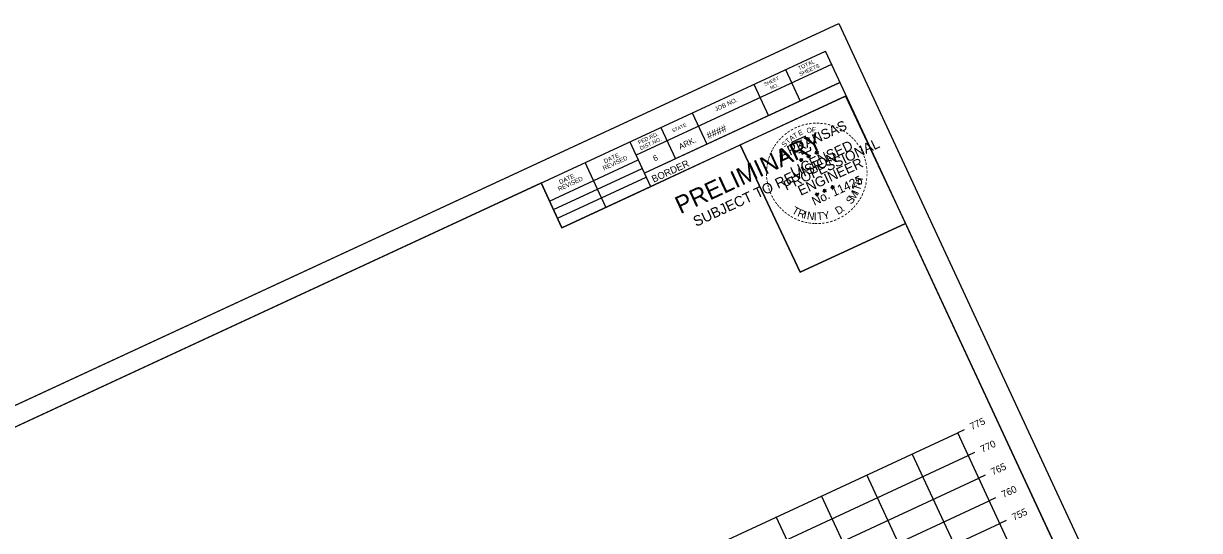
# Model space of a CAD drawing. Extents: x 1354696 to 1366163, y 660729 to 670380.
# Drawn here: x 1357962.4 to 1358197.6, y 666355.4 to 666456.9 of the extents above; entities that cross this region are included whole.
import ezdxf

# ---------------------------------------------------------------- set-up
doc = ezdxf.new("R2010")
doc.units = 0
for name, color, linetype in [('R_Axis', 7, 'Continuous'), ('R_Axis Annot', 7, 'Continuous'), ('R_Border', 7, 'Continuous'), ('R_Border PE', 7, 'Continuous'), ('R_Border Prem', 7, 'Continuous'), ('R_Grid', 7, 'Continuous'), ('R_No Plot', 7, 'Continuous')]:
    doc.layers.add(name, color=color, linetype=linetype)

msp = doc.modelspace()

# ---------------------------------------------------------------- linework, layer by layer
at = {"layer": 'R_Axis'}
for p, q in [((1358150.49, 666375.58), (1358149.22, 666374.99)), ((1358168.17, 666334.17), (1358149.22, 666374.99)), ((1358152.59, 666371.04), (1358151.32, 666370.46)), ((1358154.7, 666366.51), (1358153.43, 666365.92)), ((1358156.8, 666361.97), (1358155.53, 666361.39)), ((1358158.91, 666357.44), (1358157.64, 666356.85))]:
    msp.add_line(p, q, dxfattribs=at)
at = {"layer": 'R_Border'}
for p, q in [((1357835.98, 666318.27), (1358122.76, 666451.41)), ((1358209.28, 666265.06), (1358122.76, 666451.41)), ((1358123.99, 666448.75), (1358084.9, 666430.6)), ((1358123.99, 666448.76), (1358123.99, 666448.76)), ((1358114.77, 666447.71), (1358117.7, 666441.41)), ((1358125.68, 666445.12), (1358086.59, 666426.97)), ((1358089.27, 666428.22), (1358125.68, 666445.12)), ((1358108.48, 666444.78), (1358111.4, 666438.49)), ((1358126.92, 666442.45), (1358070.1, 666416.07)), ((1358096.16, 666439.07), (1358099.08, 666432.77)), ((1358089.87, 666436.14), (1358092.79, 666429.85)), ((1358083.66, 666433.26), (1358087.82, 666424.3)), ((1358067.63, 666421.39), (1358085.36, 666429.62)), ((1358078.88, 666420.15), (1358074.72, 666429.11)), ((1358068.42, 666419.7), (1358086.14, 666427.93)), ((1358070.1, 666416.07), (1358065.94, 666425.04)), ((1358069.23, 666417.94), (1358086.96, 666426.17)), ((1357974.42, 666382.26), (1357974.42, 666382.26)), ((1357974.42, 666382.26), (1357974.42, 666382.26))]:
    msp.add_line(p, q, dxfattribs=at)
at = {"layer": 'R_Border PE'}
for p, q in [((1358117.56, 666429.57), (1358117.8, 666429.63)), ((1358117.56, 666429.57), (1358117.92, 666429.61)), ((1358117.56, 666429.57), (1358117.82, 666429.56)), ((1358117.92, 666429.61), (1358117.77, 666429.94)), ((1358117.77, 666429.94), (1358117.92, 666429.74)), ((1358117.77, 666429.94), (1358117.83, 666429.7)), ((1358117.85, 666429.25), (1358117.92, 666429.61)), ((1358117.85, 666429.25), (1358117.95, 666429.54)), ((1358117.85, 666429.25), (1358117.86, 666429.53)), ((1358118.19, 666429.86), (1358117.92, 666429.61)), ((1358118.24, 666429.43), (1358117.92, 666429.61)), ((1358118.19, 666429.86), (1358117.95, 666429.7)), ((1358118.24, 666429.43), (1358117.95, 666429.54)), ((1358118.24, 666429.43), (1358117.99, 666429.64)), ((1358118.19, 666429.86), (1358118.05, 666429.68)), ((1358119.07, 666430.27), (1358119.32, 666430.34)), ((1358119.07, 666430.27), (1358119.43, 666430.32)), ((1358119.07, 666430.27), (1358119.34, 666430.26)), ((1358119.43, 666430.32), (1358119.28, 666430.65)), ((1358119.28, 666430.65), (1358119.43, 666430.44)), ((1358119.28, 666430.65), (1358119.35, 666430.4)), ((1358119.36, 666429.96), (1358119.43, 666430.32)), ((1358119.36, 666429.96), (1358119.47, 666430.24)), ((1358119.36, 666429.96), (1358119.37, 666430.23)), ((1358119.7, 666430.56), (1358119.43, 666430.32)), ((1358119.75, 666430.14), (1358119.43, 666430.32)), ((1358119.7, 666430.56), (1358119.46, 666430.4)), ((1358119.75, 666430.14), (1358119.47, 666430.24)), ((1358119.75, 666430.14), (1358119.51, 666430.34)), ((1358119.7, 666430.56), (1358119.56, 666430.39)), ((1358120.68, 666431), (1358120.92, 666431.07)), ((1358120.68, 666431), (1358121.04, 666431.05)), ((1358120.68, 666431), (1358120.94, 666430.99)), ((1358121.04, 666431.05), (1358120.89, 666431.38)), ((1358120.89, 666431.38), (1358121.04, 666431.17)), ((1358120.89, 666431.38), (1358120.95, 666431.13)), ((1358120.97, 666430.69), (1358121.04, 666431.05)), ((1358120.97, 666430.69), (1358121.07, 666430.98)), ((1358120.97, 666430.69), (1358120.98, 666430.96)), ((1358121.31, 666431.3), (1358121.04, 666431.05)), ((1358121.36, 666430.87), (1358121.04, 666431.05)), ((1358121.31, 666431.3), (1358121.07, 666431.13)), ((1358121.36, 666430.87), (1358121.07, 666430.97)), ((1358121.36, 666430.87), (1358121.11, 666431.08)), ((1358121.31, 666431.3), (1358121.17, 666431.12)), ((1358124.23, 666424.18), (1358124.07, 666424.51)), ((1358124.07, 666424.51), (1358124.22, 666424.31)), ((1358124.07, 666424.51), (1358124.14, 666424.27)), ((1358124.49, 666424.43), (1358124.23, 666424.18)), ((1358124.49, 666424.43), (1358124.25, 666424.26)), ((1358124.49, 666424.43), (1358124.35, 666424.25)), ((1358120.74, 666422.7), (1358120.99, 666422.76)), ((1358120.74, 666422.7), (1358121.1, 666422.74)), ((1358120.74, 666422.7), (1358121.01, 666422.69)), ((1358121.1, 666422.74), (1358120.95, 666423.07)), ((1358120.95, 666423.07), (1358121.1, 666422.87)), ((1358120.95, 666423.07), (1358121.02, 666422.83)), ((1358121.03, 666422.38), (1358121.1, 666422.74)), ((1358121.03, 666422.38), (1358121.14, 666422.67)), ((1358121.03, 666422.38), (1358121.05, 666422.66)), ((1358121.37, 666422.99), (1358121.1, 666422.74)), ((1358121.42, 666422.56), (1358121.1, 666422.74)), ((1358121.37, 666422.99), (1358121.13, 666422.83)), ((1358121.42, 666422.56), (1358121.14, 666422.67)), ((1358121.42, 666422.56), (1358121.18, 666422.77)), ((1358121.37, 666422.99), (1358121.23, 666422.81)), ((1358122.26, 666423.4), (1358122.5, 666423.47)), ((1358122.26, 666423.4), (1358122.62, 666423.45)), ((1358122.26, 666423.4), (1358122.52, 666423.39)), ((1358122.62, 666423.45), (1358122.46, 666423.78)), ((1358122.46, 666423.78), (1358122.61, 666423.57)), ((1358122.46, 666423.78), (1358122.53, 666423.53)), ((1358122.55, 666423.09), (1358122.62, 666423.45)), ((1358122.55, 666423.09), (1358122.65, 666423.37)), ((1358122.55, 666423.09), (1358122.56, 666423.36)), ((1358122.89, 666423.69), (1358122.62, 666423.45)), ((1358122.94, 666423.27), (1358122.62, 666423.45)), ((1358122.89, 666423.69), (1358122.65, 666423.53)), ((1358122.94, 666423.27), (1358122.65, 666423.37)), ((1358122.94, 666423.27), (1358122.69, 666423.47)), ((1358122.89, 666423.69), (1358122.74, 666423.51)), ((1358123.86, 666424.13), (1358124.11, 666424.2)), ((1358123.86, 666424.13), (1358124.23, 666424.18)), ((1358123.86, 666424.13), (1358124.13, 666424.12)), ((1358124.15, 666423.82), (1358124.23, 666424.18)), ((1358124.15, 666423.82), (1358124.26, 666424.11)), ((1358124.15, 666423.82), (1358124.17, 666424.1)), ((1358124.54, 666424), (1358124.23, 666424.18)), ((1358124.54, 666424), (1358124.26, 666424.11)), ((1358124.54, 666424), (1358124.3, 666424.21))]:
    msp.add_line(p, q, dxfattribs=at)
for points in [[(1358119.53, 666433.74), (1358119.54, 666434.06), (1358118.93, 666433.75), (1358118.79, 666434.41), (1358115.96, 666433.1)], [(1358115.96, 666433.1), (1358116.55, 666432.47)], [(1358117.43, 666431.11), (1358117.46, 666431.03), (1358117.98, 666431.25), (1358118.13, 666430.8), (1358119.83, 666431.59), (1358119.79, 666432.16)], [(1358117.77, 666429.94), (1358118.24, 666429.43), (1358117.56, 666429.57), (1358118.19, 666429.86), (1358117.85, 666429.25), (1358117.77, 666429.94)], [(1358119.28, 666430.65), (1358119.75, 666430.14), (1358119.07, 666430.27), (1358119.7, 666430.56), (1358119.36, 666429.96), (1358119.28, 666430.65)], [(1358120.89, 666431.38), (1358121.36, 666430.87), (1358120.68, 666431), (1358121.31, 666431.3), (1358120.97, 666430.69), (1358120.89, 666431.38)], [(1358124.07, 666424.51), (1358124.54, 666424), (1358123.86, 666424.13), (1358124.49, 666424.43), (1358124.15, 666423.82), (1358124.07, 666424.51)], [(1358120.95, 666423.07), (1358121.42, 666422.56), (1358120.74, 666422.7), (1358121.37, 666422.99), (1358121.03, 666422.38), (1358120.95, 666423.07)], [(1358122.46, 666423.78), (1358122.94, 666423.27), (1358122.26, 666423.4), (1358122.89, 666423.69), (1358122.55, 666423.09), (1358122.46, 666423.78)]]:
    msp.add_lwpolyline(points, dxfattribs=at)
for centre, radius in [((1358117.92, 666429.61), 0.172), ((1358117.92, 666429.61), 0.145), ((1358117.92, 666429.61), 0.116), ((1358117.92, 666429.61), 0.0991), ((1358117.92, 666429.61), 0.0747), ((1358117.92, 666429.61), 0.0495), ((1358117.92, 666429.61), 0.0296), ((1358119.43, 666430.32), 0.172), ((1358119.43, 666430.32), 0.145), ((1358119.43, 666430.32), 0.116), ((1358119.43, 666430.32), 0.0991), ((1358119.43, 666430.32), 0.0747), ((1358119.43, 666430.32), 0.0495), ((1358119.43, 666430.32), 0.0296), ((1358121.04, 666431.05), 0.172), ((1358121.04, 666431.05), 0.145), ((1358121.04, 666431.05), 0.116), ((1358121.04, 666431.05), 0.0991), ((1358121.04, 666431.05), 0.0747), ((1358121.04, 666431.05), 0.0495), ((1358121.04, 666431.05), 0.0296), ((1358121.1, 666422.74), 0.172), ((1358121.1, 666422.74), 0.145), ((1358121.1, 666422.74), 0.116), ((1358121.1, 666422.74), 0.0991), ((1358121.1, 666422.74), 0.0747), ((1358121.1, 666422.74), 0.0495), ((1358121.1, 666422.74), 0.0296), ((1358122.62, 666423.44), 0.172), ((1358122.62, 666423.44), 0.145), ((1358122.62, 666423.44), 0.116), ((1358122.62, 666423.44), 0.0991), ((1358122.62, 666423.44), 0.0747), ((1358122.62, 666423.44), 0.0495), ((1358122.62, 666423.44), 0.0296), ((1358124.22, 666424.18), 0.172), ((1358124.22, 666424.18), 0.145), ((1358124.22, 666424.18), 0.116), ((1358124.22, 666424.18), 0.0991), ((1358124.22, 666424.18), 0.0747), ((1358124.22, 666424.18), 0.0495), ((1358124.22, 666424.18), 0.0296)]:
    msp.add_circle(centre, radius, dxfattribs=at)
at = {"layer": 'R_Grid'}
for p, q in [((1357877.11, 666248.66), (1358149.22, 666374.99)), ((1358168.17, 666334.17), (1358149.22, 666374.99)), ((1357879.22, 666244.12), (1358151.32, 666370.46)), ((1358159.1, 666329.96), (1358140.15, 666370.78)), ((1357881.32, 666239.59), (1358153.43, 666365.92)), ((1358150.03, 666325.75), (1358131.08, 666366.57)), ((1357883.43, 666235.05), (1358155.53, 666361.39)), ((1358140.96, 666321.54), (1358122.01, 666362.36)), ((1357885.54, 666230.52), (1358157.64, 666356.85)), ((1358131.89, 666317.33), (1358112.94, 666358.15))]:
    msp.add_line(p, q, dxfattribs=at)
at = {"layer": 'R_No Plot'}
for p, q in [((1357823.09, 666316.58), (1358125.43, 666456.95)), ((1358114.63, 666411.99), (1358114.63, 666411.99))]:
    msp.add_line(p, q, dxfattribs=at)
for points in [[(1357823.08, 666316.58), (1358125.43, 666456.95), (1358215.26, 666263.45), (1357912.92, 666123.08)], [(1358105.76, 666432.63), (1358126.81, 666442.4), (1358138.77, 666416.91), (1358117.72, 666407.14)], [(1358048.14, 666416.77), (1358065.94, 666425.04), (1358070.1, 666416.07), (1358084.71, 666422.86), (1358105.76, 666432.63), (1358117.72, 666407.14), (1358138.77, 666416.91), (1358209.28, 666265.06), (1357922.5, 666131.91), (1357835.98, 666318.27)]]:
    msp.add_lwpolyline(points, close=True, dxfattribs=at)

# ---------------------------------------------------------------- texts
at = {"layer": 'R_Axis Annot'}
for s, p in [('775', (1358152.05, 666375.53)), ('770', (1358154.16, 666371)), ('765', (1358156.26, 666366.46)), ('760', (1358158.37, 666361.93)), ('755', (1358160.47, 666357.39))]:
    msp.add_text(s, height=1.4, rotation=24.9042, dxfattribs=at).set_placement(p)
at = {"layer": 'R_Border'}
for s, height, p in [('TOTAL', 0.782, (1358117.53, 666447.57)), ('SHEETS', 0.782, (1358117.77, 666446.39)), ('SHEET', 0.684, (1358110.71, 666444.41)), ('NO.', 0.684, (1358111.91, 666443.67)), ('JOB NO.', 0.879, (1358100.89, 666439.32)), ('STATE', 0.684, (1358092.29, 666435.11)), ('####', 1.4, (1358099.4, 666433.74)), ('FED.RD.', 0.782, (1358085.54, 666432.73)), ('DIST.NO.', 0.782, (1358085.86, 666431.57)), ('ARK.', 1.172, (1358093.76, 666431.69)), ('REVISED', 0.879, (1358078.49, 666427.5)), ('DATE', 0.879, (1358078.7, 666428.9)), ('BORDER', 1.4, (1358088.43, 666425.06)), ('6', 1.17, (1358088.63, 666429.31)), ('DATE', 0.879, (1358069.75, 666424.75)), ('REVISED', 0.879, (1358069.54, 666423.35))]:
    msp.add_text(s, height=height, rotation=24.9042, dxfattribs=at).set_placement(p)
at = {"layer": 'R_Border PE'}
for s, height, rotation, p in [('ARKANSAS', 2, 24.9042, (1358114.07, 666429.7)), ('-', 1.6, 25.0904, (1358116.76, 666435.36)), ('-', 1.6, 22.6472, (1358117.42, 666435.65)), ('-', 1.6, 17.0659, (1358118.12, 666435.92)), ('-', 1.6, 12.1091, (1358118.82, 666436.12)), ('-', 1.6, 7.2404, (1358119.46, 666436.24)), ('F', 1, 4.9748, (1358120.1, 666435.13)), ('-', 1.6, 2.7593, (1358120.22, 666436.35)), ('-', 1.6, 359.0253, (1358120.91, 666436.37)), ('-', 1.6, 354.5451, (1358121.55, 666436.36)), ('-', 1.6, 350.7668, (1358122.29, 666436.3)), ('-', 1.6, 345.4339, (1358123.02, 666436.17)), ('-', 1.6, 340.4828, (1358123.77, 666435.98)), ('-', 1.6, 334.7839, (1358124.52, 666435.72)), ('-', 1.6, 49.2114, (1358113.89, 666433.09)), ('-', 1.6, 44.0802, (1358114.35, 666433.6)), ('-', 1.6, 38.5343, (1358114.93, 666434.13)), ('T', 1, 41.3078, (1358115.29, 666432.8)), ('-', 1.6, 35.1235, (1358115.48, 666434.56)), ('A', 1, 36.1173, (1358115.94, 666433.38)), ('-', 1.6, 30.801, (1358116.09, 666434.97)), ('T', 1, 30.9269, (1358116.64, 666433.89)), ('E', 1, 25.7365, (1358117.59, 666434.45)), ('O', 1, 15.3557, (1358119.14, 666434.94)), ('-', 1.6, 331.5563, (1358125.25, 666435.4)), ('-', 1.4, 328.5795, (1358125.93, 666435.09)), ('-', 1.6, 324.5725, (1358126.47, 666434.67)), ('-', 1.6, 319.567, (1358127.02, 666434.25)), ('-', 1.6, 315.477, (1358127.5, 666433.84)), ('-', 1.6, 310.0274, (1358127.96, 666433.41)), ('-', 1.6, 63.8548, (1358112.43, 666430.8)), ('-', 1.6, 61.1359, (1358112.7, 666431.34)), ('-', 1.6, 58.9677, (1358113.06, 666431.95)), ('-', 1.6, 53.696, (1358113.45, 666432.53)), ('S', 1, 46.4982, (1358114.6, 666432.12)), ('PROFESSIONAL', 2, 24.9042, (1358114.96, 666423.44)), ('LICENSED', 2, 24.9042, (1358116.36, 666426.19)), ('-', 1.6, 305.4535, (1358128.45, 666432.82)), ('-', 1.6, 301.5003, (1358128.92, 666432.19)), ('-', 1.6, 299.2343, (1358129.28, 666431.56)), ('-', 1.6, 75.5183, (1358111.85, 666429.01)), ('-', 1.6, 73.3272, (1358112.01, 666429.62)), ('-', 1.6, 67.8664, (1358112.21, 666430.24)), ('ENGINEER', 2, 24.9042, (1358117.84, 666422.44)), ('DWB', 0.01, 24.9042, (1358117.91, 666429.6)), ('DWB', 0.01, 24.9042, (1358119.42, 666430.31)), ('DWB', 0.01, 24.9042, (1358121.03, 666431.04)), ('-', 1.6, 294.8448, (1358129.58, 666431)), ('-', 1.6, 288.4214, (1358129.84, 666430.39)), ('-', 1.6, 285.8995, (1358130.05, 666429.77)), ('-', 1.6, 280.6668, (1358130.24, 666429.11)), ('-', 1.6, 92.6784, (1358111.64, 666426.35)), ('-', 1.6, 87.7755, (1358111.61, 666427.02)), ('-', 1.6, 82.9748, (1358111.64, 666427.7)), ('-', 1.6, 79.1366, (1358111.71, 666428.32)), ('-', 1.6, 277.7723, (1358130.37, 666428.38)), ('-', 1.6, 272.7928, (1358130.46, 666427.67)), ('-', 1.6, 269.5239, (1358130.48, 666426.99)), ('-', 1.6, 97.2986, (1358111.7, 666425.69)), ('-', 1.6, 100.3651, (1358111.83, 666424.96)), ('-', 1.6, 106.1054, (1358112.01, 666424.26)), ('No. 11425', 1.757, 24.9042, (1358120.56, 666420.44)), ('T', 1.54, 71.5486, (1358129.64, 666423.32)), ('H', 1.54, 79.513, (1358130.05, 666424.55)), ('-', 1.6, 256.1579, (1358130.2, 666424.69)), ('-', 1.6, 258.7494, (1358130.35, 666425.38)), ('-', 1.6, 263.9754, (1358130.44, 666426.14)), ('-', 1.6, 110.0905, (1358112.23, 666423.6)), ('-', 1.6, 113.9664, (1358112.5, 666422.95)), ('-', 1.6, 119.1, (1358112.84, 666422.31)), ('DWB', 0.01, 24.9042, (1358121.1, 666422.73)), ('DWB', 0.01, 24.9042, (1358122.61, 666423.44)), ('DWB', 0.01, 24.9042, (1358124.22, 666424.17)), ('S', 1.54, 51.8354, (1358127.94, 666420.62)), ('M', 1.54, 57.5605, (1358128.53, 666421.35)), ('I', 1.54, 67.0178, (1358129.34, 666422.65)), ('-', 1.6, 240.6405, (1358129.45, 666422.63)), ('-', 1.6, 245.9893, (1358129.74, 666423.29)), ('-', 1.6, 250.6695, (1358130, 666423.97)), ('-', 1.6, 123.8521, (1358113.18, 666421.73)), ('-', 1.6, 126.6191, (1358113.61, 666421.12)), ('-', 1.6, 130.362, (1358114.01, 666420.65)), ('-', 1.6, 133.9916, (1358114.47, 666420.17)), ('-', 1.6, 138.9685, (1358114.95, 666419.74)), ('T', 1.54, 330.9447, (1358115.93, 666419.06)), ('R', 1.54, 338.9091, (1358117.07, 666418.43)), ('D', 1.54, 31.3011, (1358125.3, 666418.59)), ('-', 1.6, 225.6226, (1358127.89, 666420.45)), ('-', 1.6, 229.1558, (1358128.33, 666420.96)), ('-', 1.6, 232.261, (1358128.76, 666421.51)), ('-', 1.6, 237.1533, (1358129.12, 666422.06)), ('-', 1.6, 140.633, (1358115.49, 666419.31)), ('-', 1.6, 145.3513, (1358116.06, 666418.92)), ('-', 1.6, 150.7976, (1358116.66, 666418.59)), ('-', 1.6, 155.6223, (1358117.32, 666418.28)), ('-', 1.6, 159.128, (1358118.01, 666418)), ('-', 1.6, 163.838, (1358118.69, 666417.8)), ('I', 1.54, 346.8735, (1358118.28, 666417.97)), ('N', 1.54, 351.4044, (1358118.99, 666417.78)), ('I', 1.54, 0.2645, (1358120.42, 666417.57)), ('T', 1.54, 4.7953, (1358121.15, 666417.55)), ('Y', 1.54, 12.7597, (1358122.44, 666417.66)), ('-', 1.6, 198.0196, (1358124.11, 666418.02)), ('-', 1.6, 201.4224, (1358124.82, 666418.29)), ('-', 1.6, 206.4959, (1358125.48, 666418.62)), ('-', 1.6, 210.7208, (1358126.18, 666419.03)), ('.', 1.54, 38.6683, (1358126.33, 666419.21)), ('-', 1.6, 216.1899, (1358126.8, 666419.46)), ('-', 1.6, 220.3785, (1358127.37, 666419.94)), ('-', 1.6, 169.5505, (1358119.36, 666417.67)), ('-', 1.6, 172.9939, (1358120.03, 666417.57)), ('-', 1.6, 176.4746, (1358120.69, 666417.52)), ('-', 1.6, 179.5044, (1358121.26, 666417.51)), ('-', 1.6, 183.4654, (1358121.94, 666417.55)), ('-', 1.6, 187.7024, (1358122.65, 666417.64)), ('-', 1.6, 192.4597, (1358123.37, 666417.79))]:
    msp.add_text(s, height=height, rotation=rotation, dxfattribs=at).set_placement(p)
at = {"layer": 'R_Border Prem'}
for s, height, p in [('PRELIMINARY', 3.5, (1358093.76, 666418.75)), ('SUBJECT TO REVISION', 2.0751, (1358096.93, 666416.22)), ('DWB', 0.01, (1358093.66, 666420.74))]:
    msp.add_text(s, height=height, rotation=24.9042, dxfattribs=at).set_placement(p)

doc.saveas('drawing.dxf')
